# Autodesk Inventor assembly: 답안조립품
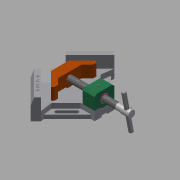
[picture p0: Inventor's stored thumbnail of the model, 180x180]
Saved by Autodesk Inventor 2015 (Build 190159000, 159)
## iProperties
Created: 2020-05
Part Number: 답안조립품
Document SubType Name: Assembly
Designer: CAD02
Author: CAD02
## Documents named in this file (11)
- C:\Users\CAD02\Desktop\700506V1048\답안조립품.iam
- C:\Users\CAD02\Desktop\700506V1048\리드스크류.ipt
- C:\Users\CAD02\Desktop\700506V1048\멈춤나사 M4x5.ipt
- C:\Users\CAD02\Desktop\700506V1048\멈춤나사 M4x10.ipt
- C:\Users\CAD02\Desktop\700506V1048\베이스.ipt
- C:\Users\CAD02\Desktop\700506V1048\볼트 M4x16.ipt
- C:\Users\CAD02\Desktop\700506V1048\부시.ipt
- C:\Users\CAD02\Desktop\700506V1048\서포트.ipt
- C:\Users\CAD02\Desktop\700506V1048\조.ipt
- C:\Users\CAD02\Desktop\700506V1048\평행 핀 2.5x24.ipt
- C:\Users\CAD02\Desktop\700506V1048\핸들.ipt
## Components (1 placed, 1 different names)
1. 핸들:1
